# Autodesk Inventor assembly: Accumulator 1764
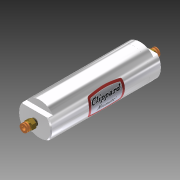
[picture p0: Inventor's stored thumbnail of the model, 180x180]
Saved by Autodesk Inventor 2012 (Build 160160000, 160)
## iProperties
Created: 2010-01
Part Number: Accumulator 1764
Document SubType Name: Assembly
Designer: cmcfadden
Author: cmcfadden
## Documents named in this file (4)
- R:\CAD Archives\Pneumatics_1764\Accumulator_1764\Accumulator_1764.iam
- R:\CAD Archives\Pneumatics_1764\Accumulator_1764\Pneumatic_Screw_1764\Pneumatic_Screw_1764.iam
- R:\CAD Archives\Pneumatics_1764\Accumulator_1764\Accumulator_Tank_1764.ipt
- R:\CAD Archives\Pneumatics_1764\Accumulator_1764\Accumulator_Cap_1764.ipt
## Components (5 placed, 3 different names)
1. Accumulator_Tank_1764:1 — Mate:1, Tangent:1, Mate:2, Tangent:2
2. Accumulator_Cap_1764:1 — Mate:1, Tangent:1, Mate:4, Mate:6
3. Accumulator_Cap_1764:2 — Mate:2, Tangent:2, Mate:3, Mate:5
4. Pneumatic_Screw_1764:1 [sub-assembly] — Mate:3, Mate:5
5. Pneumatic_Screw_1764:2 [sub-assembly] — Mate:4, Mate:6
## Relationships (8: Mate 6, Tangent 2)
- Mate:1: Accumulator_Tank_1764:1 ↔ Accumulator_Cap_1764:1
- Tangent:1: Accumulator_Tank_1764:1 ↔ Accumulator_Cap_1764:1
- Mate:2: Accumulator_Tank_1764:1 ↔ Accumulator_Cap_1764:2
- Tangent:2: Accumulator_Tank_1764:1 ↔ Accumulator_Cap_1764:2
- Mate:3: Accumulator_Cap_1764:2 ↔ Pneumatic_Screw_1764:1
- Mate:4: Accumulator_Cap_1764:1 ↔ Pneumatic_Screw_1764:2
- Mate:5: Accumulator_Cap_1764:2 ↔ Pneumatic_Screw_1764:1
- Mate:6: Accumulator_Cap_1764:1 ↔ Pneumatic_Screw_1764:2
